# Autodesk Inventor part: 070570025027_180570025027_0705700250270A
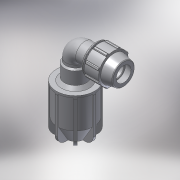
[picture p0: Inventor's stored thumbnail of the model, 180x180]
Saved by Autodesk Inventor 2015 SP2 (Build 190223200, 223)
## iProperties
Created: 2017-02
Part Number: 070570025027_180570025027_0705700250270A
Material: PVC-Piping
Description: PLASSON PLASS4 90° ELBOW 20-27*25
Document SubType Name: Modeling
Designer: KIM
Mass: 92.6774 g
Surface Area: 199.44 cm^2
Volume: 66.1981 cm^3
Density: 1.4 g/cm^3
Appearance: Smooth - White
Author: KIM
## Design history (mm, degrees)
derived "070570.ipt"
feature "Solid1::070570.ipt"
tag "TaggingFeature1"
body "Solid1"
other parameters: "d2" = 25, "d4" = 11.57143, "d5" = 16.2, "d7" = 54, "d8" = 32.54092, "d9" = 11.57143, "d11" = 2.31429, "d12" = 43.2, "d13" = 120 deg, "d14" = 37.5, "d15" = 12 deg, "d16" = 48.6, "d18" = 1.25, "d19" = 35 deg, "d20" = 17.5 deg, "d21" = 50.22, "d23" = 0, "d25" = 360 deg, "d27" = 1.08, "d42" = 24.3, "d43" = 1.62, "d46" = 0.75, "d53" = 0.5, "d67" = 2.7, "d70" = 22.5, "d71" = 58, "d73" = 81, "d74" = 90 deg, "d75" = 27, "d76" = 71, "d77" = 139, "d78" = 4.05, "d80" = 22.5, "d82" = 105, "d84" = 67.45, "d85" = 135 deg, "d86" = 3.55, "d88" = 105, "d89" = 3.55, "d90" = 135 deg, "d91" = 78.75, "d92" = 22.24, "d93" = 26.25, "d94" = 3.55, "d95" = 5.25, "d97" = 4.32, "d98" = 0, "d100" = 360 deg, "d102" = 78.1, "d103" = 14.2, "d104" = 5.68, "d105" = 0, "d107" = 16.2, "d108" = 0, "d109" = 0, "d_" = 25, "E_" = 54, "A_" = 81, "l_" = 58, "d_1" = 27, "E_1" = 71, "l_1" = 105, "A_1" = 139, "d106" = 32.54092
